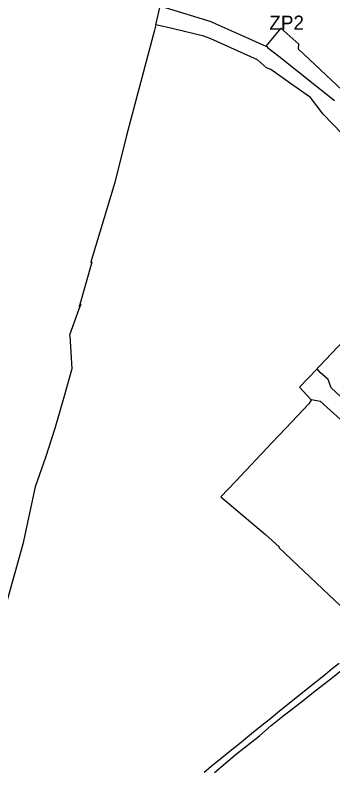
# Model space of a CAD drawing. Extents: x 7413438 to 7416393, y 5541665 to 5544118.
# Drawn here: x 7414051.4 to 7414186.3, y 5542752 to 5543072.4 of the extents above; entities that cross this region are included whole.
import ezdxf

# ---------------------------------------------------------------- set-up
doc = ezdxf.new("R2010")
doc.units = 0
for name, color, linetype in [('linie_rozgraniczajace', 7, 'Continuous'), ('linie_zabudowy_nieprzekraczalne', 7, 'Continuous'), ('oznaczenia_przeznaczen', 7, 'Continuous')]:
    doc.layers.add(name, color=color, linetype=linetype)

msp = doc.modelspace()

# ---------------------------------------------------------------- linework, layer by layer
at = {"layer": 'linie_rozgraniczajace'}
for p, q in [((7414111.14, 5543068.38), (7414112.92, 5543076.24)), ((7414115.08, 5543075.66), (7414134.44, 5543069.73)), ((7414111.14, 5543068.38), (7414110.64, 5543066.13)), ((7414118.6, 5543066.6), (7414111.14, 5543068.38)), ((7414134.44, 5543069.73), (7414134.43, 5543069.76)), ((7414134.43, 5543069.76), (7414136.59, 5543068.82)), ((7414136.59, 5543068.82), (7414148.07, 5543063.65)), ((7414110.64, 5543066.13), (7414098.68, 5543021.43)), ((7414131.58, 5543063.56), (7414118.6, 5543066.6)), ((7414164.23, 5543066.98), (7414157.81, 5543059.27)), ((7414171.85, 5543060.13), (7414164.23, 5543066.98)), ((7414134.44, 5543062.35), (7414131.58, 5543063.56)), ((7414154.29, 5543053.45), (7414134.44, 5543062.35)), ((7414148.07, 5543063.65), (7414157.81, 5543059.27)), ((7414157.81, 5543059.27), (7414158.21, 5543059.09)), ((7414158.21, 5543059.09), (7414158.53, 5543058.68)), ((7414158.53, 5543058.68), (7414163.36, 5543055.1)), ((7414171.66, 5543057.97), (7414171.85, 5543060.13)), ((7414190.36, 5543040.51), (7414171.66, 5543057.97)), ((7414163.36, 5543055.1), (7414187.05, 5543036.24)), ((7414158.11, 5543050.14), (7414154.29, 5543053.45)), ((7414160.01, 5543049.46), (7414158.11, 5543050.14)), ((7414168.3, 5543043.41), (7414160.01, 5543049.46)), ((7414176.75, 5543037.53), (7414168.3, 5543043.41)), ((7414182.16, 5543030.42), (7414176.75, 5543037.53)), ((7414182.22, 5543030.49), (7414182.16, 5543030.42)), ((7414190.14, 5543022.24), (7414182.22, 5543030.49)), ((7414098.68, 5543021.43), (7414093.66, 5543001.5)), ((7414093.66, 5543001.5), (7414089.24, 5542986.49)), ((7414089.24, 5542986.49), (7414083.63, 5542968.26)), ((7414083.63, 5542968.26), (7414083.59, 5542967.58)), ((7414083.93, 5542967.78), (7414084.11, 5542967.88)), ((7414084.11, 5542967.88), (7414083.95, 5542967.68)), ((7414083.95, 5542967.68), (7414078.61, 5542948.8)), ((7414083.59, 5542967.58), (7414083.93, 5542967.78)), ((7414079.28, 5542949.87), (7414078.5, 5542947.74)), ((7414078.61, 5542948.8), (7414079.28, 5542949.87)), ((7414078.5, 5542947.74), (7414074.44, 5542936.7)), ((7414203.63, 5542947.88), (7414185.7, 5542928.99)), ((7414074.44, 5542936.7), (7414074.57, 5542936.67)), ((7414074.57, 5542936.67), (7414075.48, 5542922.54)), ((7414185.7, 5542928.99), (7414180.78, 5542923.8)), ((7414180.78, 5542923.8), (7414179.63, 5542922.59)), ((7414075.48, 5542922.54), (7414072.19, 5542910.86)), ((7414179.63, 5542922.56), (7414172.15, 5542914.67)), ((7414179.63, 5542922.59), (7414179.67, 5542922.56)), ((7414180.91, 5542921), (7414179.63, 5542922.56)), ((7414179.67, 5542922.56), (7414179.63, 5542922.56)), ((7414184.27, 5542918), (7414180.91, 5542921)), ((7414185.53, 5542914.43), (7414184.27, 5542918)), ((7414172.15, 5542914.67), (7414176.96, 5542909.5)), ((7414199.85, 5542901.18), (7414185.53, 5542914.43)), ((7414072.19, 5542910.86), (7414068.24, 5542897.2)), ((7414176.03, 5542907.6), (7414166.31, 5542897.35)), ((7414177.23, 5542909.45), (7414176.03, 5542907.6)), ((7414176.96, 5542909.5), (7414177.23, 5542909.45)), ((7414177.23, 5542909.45), (7414180.96, 5542908.72)), ((7414180.96, 5542908.72), (7414201.08, 5542890.47)), ((7414166.31, 5542897.35), (7414160.43, 5542891.14)), ((7414068.24, 5542897.2), (7414064.24, 5542884.86)), ((7414160.43, 5542891.14), (7414144.92, 5542874.79)), ((7414064.24, 5542884.86), (7414059.97, 5542872.5)), ((7414059.97, 5542872.5), (7414054.61, 5542848.19)), ((7414144.92, 5542874.79), (7414138.76, 5542868.3)), ((7414138.76, 5542868.3), (7414157.75, 5542852.2)), ((7414157.75, 5542852.2), (7414163.51, 5542847.01)), ((7414054.61, 5542848.19), (7414046.86, 5542820.34)), ((7414163.51, 5542847.01), (7414163.36, 5542846.81)), ((7414163.36, 5542846.81), (7414184.57, 5542826.67)), ((7414184.57, 5542826.67), (7414184.6, 5542826.64)), ((7414184.6, 5542826.64), (7414202.12, 5542810.03)), ((7414186.21, 5542795.42), (7414183.16, 5542792.97)), ((7414184.82, 5542790.69), (7414190.4, 5542795.09)), ((7414188.91, 5542797.58), (7414186.21, 5542795.42)), ((7414183.16, 5542792.97), (7414175.65, 5542786.96)), ((7414178.81, 5542785.98), (7414184.82, 5542790.69)), ((7414175.65, 5542786.96), (7414168.41, 5542781.16)), ((7414172.95, 5542781.36), (7414178.81, 5542785.98)), ((7414168.41, 5542781.16), (7414163.67, 5542777.36)), ((7414165.13, 5542775.21), (7414172.95, 5542781.36)), ((7414163.67, 5542777.36), (7414159.24, 5542773.74)), ((7414159.24, 5542773.74), (7414156.18, 5542771.24)), ((7414160.15, 5542771.3), (7414165.13, 5542775.21)), ((7414156.18, 5542771.24), (7414151.82, 5542767.74)), ((7414155.11, 5542766.9), (7414160.15, 5542771.3)), ((7414145.45, 5542759.27), (7414155.11, 5542766.9)), ((7414151.82, 5542767.74), (7414146.62, 5542763.57)), ((7414146.62, 5542763.57), (7414142.7, 5542760.43)), ((7414142.7, 5542760.43), (7414139.6, 5542757.89)), ((7414139.6, 5542757.89), (7414134.56, 5542753.76)), ((7414135.98, 5542751.39), (7414145.45, 5542759.27)), ((7414134.56, 5542753.76), (7414131.61, 5542751.34))]:
    msp.add_line(p, q, dxfattribs=at)
at = {"layer": 'linie_zabudowy_nieprzekraczalne'}
msp.add_open_spline([(7414330.5, 5542776.55), (7414327.11, 5542770.73), (7414320.65, 5542760.97), (7414307.51, 5542744.67), (7414295.2, 5542731.39), (7414289.91, 5542726.96), (7414284.38, 5542722.92), (7414270.86, 5542714.31), (7414257.24, 5542706.19), (7414247.85, 5542701.87), (7414232.05, 5542694.6), (7414206.95, 5542682.92), (7414167.63, 5542663.48)], degree=3, dxfattribs=at)

# ---------------------------------------------------------------- texts
at = {"layer": 'oznaczenia_przeznaczen'}
msp.add_text('ZP2', height=6, dxfattribs=at).set_placement((7414159.32, 5543066.23))

doc.saveas('drawing.dxf')
